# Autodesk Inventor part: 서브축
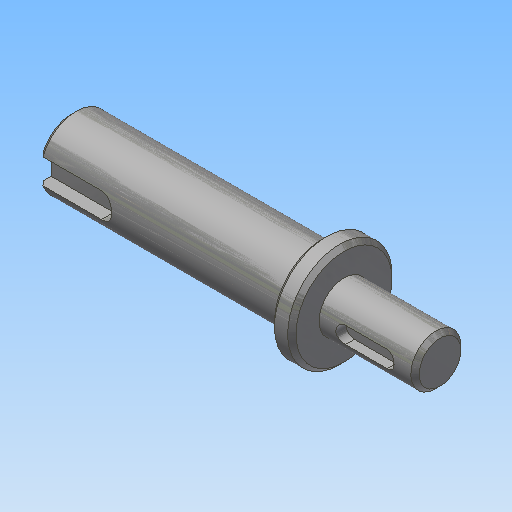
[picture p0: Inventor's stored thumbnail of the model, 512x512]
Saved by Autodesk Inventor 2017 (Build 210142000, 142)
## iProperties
Created: 2018-09
Part Number: 서브축
Document SubType Name: Modeling
Density: 1 g/cm^3
Material: 강철, 연강
Appearance: 강철
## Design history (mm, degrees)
sketch "스케치1"
  geometry: L1 (-18.818, -7)-(-18.818, 7) reference; L2 (-41.331, -13.5)-(-41.331, 13.5) reference; L3 (-46.5, 12.249)-(-46.5, -12.249) reference; L4 (-18.331, 0)-(-106.5, 0); L5 (-18.331, 0)-(-18.331, -6); L6 (-18.331, -6)-(-41.331, -6); L7 (-41.331, -12.5)-(-46.5, -12.5); L8 (-46.5, -8.5)-(-106.5, -8.5); L9 (-106.5, -8.5)-(-106.5, 0); L10 (-46.5, -8.5)-(-46.5, -12.5); L11 (-41.331, -6)-(-41.331, -12.5); 2 further points
  constraints: 17 end point, 5 point on line, 3 parallel, 3 perpendicular, 2 collinear, 1 midpoint
  dimensions: "d0" = 23 distance between parallel lines of L2 L5; "d1" = 12 diameter of L6 L4; "d2" = 25 diameter of L7 L4; "d3" = 17 diameter of L8 L4; "d4" = 60 distance of L8.start L8.end
revolve "회전1" sketch "스케치1" stored, may be unused: angle "d5" = 90 deg
chamfer "모따기1" distance "d6" = 1; stored, may be unused: second distance "d7" = 2, angle "d8" = 45 deg
node "작업 평면1"
sketch "스케치2"
  geometry: L1 (11.5, 5)-(11.5, -5) reference; L2 (-5.5, -2)-(4.5, -2); L3 (4.5, 2)-(-5.5, 2); A1 r 2 centre (4.5, 0) between (4.5, -2) and (4.5, 2); A2 r 2 centre (-5.5, 0) between (-5.5, 2) and (-5.5, -2); 2 further points
  constraints: 4 end point, 4 point on circle, 4 tangent, 2 centre point, 1 horizontal alignment, 1 midpoint, 1 parallel, 1 perpendicular
  dimensions: "d9" = 4 distance between parallel lines of L2 L3; "d10" = 14 dimension on A1 A2; "d11" = 5 distance edge to line of A1 L1
extrude "돌출1" cut sketch "스케치2" distance "d12" = 2.5; taper "d13" = 0 deg
node "작업 평면2"
sketch "스케치3"
  geometry: L1 (-30, -7.5)-(-30, 7.5) reference; L2 (-30, 3)-(-15, 3); L3 (-15, -3)-(-30, -3); A1 r 3 centre (-15, 0) between (-15, -3) and (-15, 3); 2 further points
  constraints: 4 end point, 2 perpendicular, 2 point on circle, 2 point on line, 2 tangent, 1 centre point, 1 horizontal alignment, 1 midpoint
  dimensions: "d14" = 6 distance between parallel lines of L3 L2; "d15" = 18 dimension on A1 L1
extrude "돌출2" cut sketch "스케치3" distance "d16" = 3.5; taper "d17" = 0 deg
node "솔리드1"
node "참조1"
node "참조2"
node "참조3"
